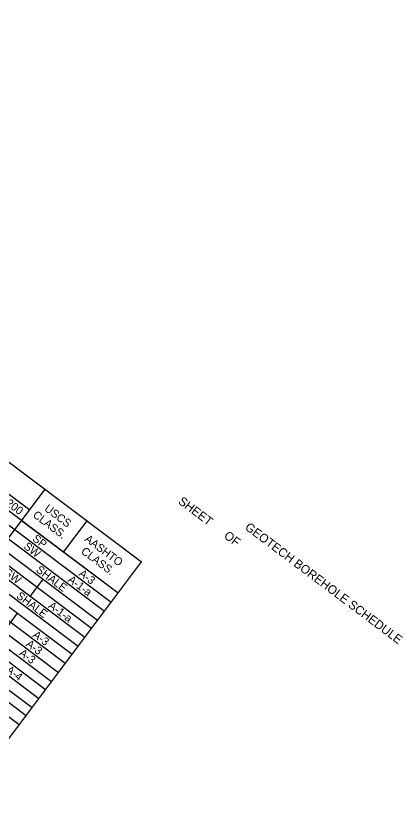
# Model space of a CAD drawing. Extents: x 627484.2 to 627517.5, y 367968.7 to 367996.9.
# Drawn here: x 627497.5 to 627500.16, y 367986.94 to 367992.47 of the extents above; entities that cross this region are included whole.
import ezdxf

# ---------------------------------------------------------------- set-up
doc = ezdxf.new("R2010")
doc.units = 0
for name, color, linetype in [('Default', 7, 'Continuous'), ('R_Survey Control', 7, 'Continuous'), ('R_Wall', 7, 'Continuous')]:
    doc.layers.add(name, color=color, linetype=linetype)

msp = doc.modelspace()

# ---------------------------------------------------------------- linework, layer by layer
at = {"layer": 'Default'}
for p, q in [((627493.1196, 367992.664), (627498.3625, 367988.727)), ((627492.9586, 367992.4496), (627498.2015, 367988.5126)), ((627492.9118, 367992.3872), (627498.1547, 367988.4503)), ((627492.8649, 367992.3248), (627498.1078, 367988.3879)), ((627492.8181, 367992.2625), (627498.061, 367988.3255)), ((627492.7771, 367992.2079), (627498.02, 367988.2709)), ((627492.7303, 367992.1455), (627497.9732, 367988.2086)), ((627492.6834, 367992.0832), (627497.9263, 367988.1462)), ((627492.6425, 367992.0286), (627497.8854, 367988.0916)), ((627492.5956, 367991.9662), (627497.8385, 367988.0293)), ((627492.5488, 367991.9038), (627497.7917, 367987.9669)), ((627492.5019, 367991.8415), (627497.7449, 367987.9045)), ((627492.461, 367991.7869), (627497.7039, 367987.8499)), ((627492.4141, 367991.7245), (627497.657, 367987.7876)), ((627492.3673, 367991.6621), (627497.6102, 367987.7252)), ((627492.3263, 367991.6076), (627497.5692, 367987.6706)), ((627492.2795, 367991.5452), (627497.5224, 367987.6082)), ((627496.0039, 367990.2787), (627497.5944, 367989.0843)), ((627495.7707, 367986.6557), (627497.6998, 367989.2247)), ((627497.5388, 367989.0103), (627498.2015, 367988.5126)), ((627497.8273, 367988.7937), (627497.9883, 367989.0081)), ((627496.4334, 367986.1581), (627498.3625, 367988.727)), ((627497.5989, 367988.4896), (627497.6868, 367988.6065)), ((627496.0592, 367986.4391), (627497.5111, 367988.3726))]:
    msp.add_line(p, q, dxfattribs=at)

# ---------------------------------------------------------------- texts
for s, p in [('#200', (627497.3926, 367989.1436)), ('USCS', (627497.69, 367989.0816)), ('CLASS.', (627497.6107, 367989.038)), ('SP', (627497.6081, 367988.8751)), ('AASHTO', (627497.967, 367988.8736)), ('SW', (627497.5478, 367988.8228)), ('CLASS.', (627497.9421, 367988.7891)), ('GW', (627497.4078, 367988.6475)), ('SHALE', (627497.6327, 367988.6615)), ('A-3', (627497.9266, 367988.6359)), ('A-1-a', (627497.8519, 367988.5944)), ('SHALE', (627497.498, 367988.4822)), ('A-1-a', (627497.7173, 367988.4151)), ('A-3', (627497.6105, 367988.2149)), ('A-3', (627497.5637, 367988.1525)), ('A-3', (627497.5168, 367988.0901)), ('A-4', (627497.4274, 367987.9743))]:
    msp.add_text(s, height=0.055, rotation=323.0968, dxfattribs=at).set_placement(p)
at = {"layer": 'R_Survey Control'}
for s, p in [('SHEET', (627498.6103, 367989.1307)), ('OF', (627498.9243, 367988.8949))]:
    msp.add_text(s, height=0.06, rotation=323.0968, dxfattribs=at).set_placement(p)
at = {"layer": 'R_Wall'}
msp.add_text('GEOTECH BOREHOLE SCHEDULE', height=0.06, rotation=323.0968, dxfattribs=at).set_placement((627499.0686, 367988.9535))

doc.saveas('drawing.dxf')
